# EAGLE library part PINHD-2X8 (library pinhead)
PIN HEADER
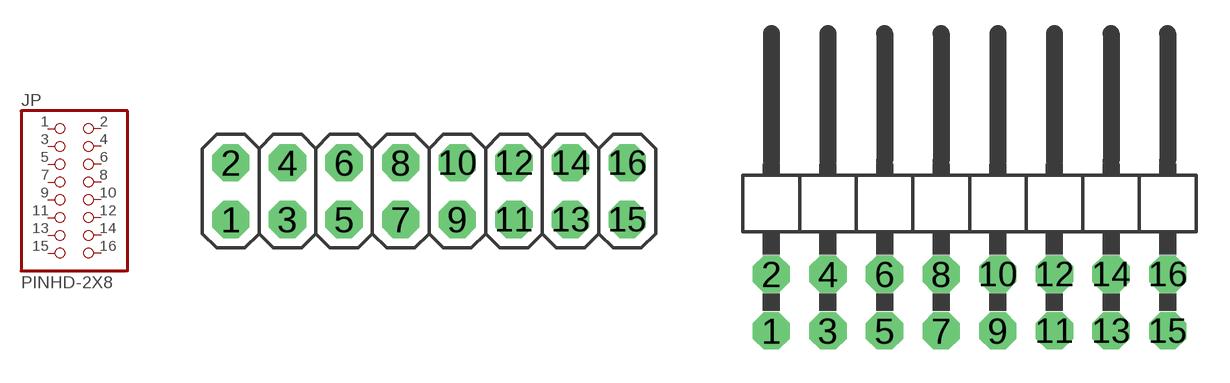
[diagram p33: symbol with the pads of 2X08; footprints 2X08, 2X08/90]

Designator prefix JP

## PINHD-2X8  [2X08]
1  1  pas
2  2  pas
3  3  pas
4  4  pas
5  5  pas
6  6  pas
7  7  pas
8  8  pas
9  9  pas
10  10  pas
11  11  pas
12  12  pas
13  13  pas
14  14  pas
15  15  pas
16  16  pas

## PINHD-2X8/90  [2X08/90]
Pads as for 2X08

## Footprint 2X08 (pad centres in mm)
PIN HEADER
drill 1.016 pad 1.67 octagon: 1 -8.89,-1.27; 2 -8.89,1.27; 3 -6.35,-1.27; 4 -6.35,1.27; 5 -3.81,-1.27; 6 -3.81,1.27; 7 -1.27,-1.27; 8 -1.27,1.27; 9 1.27,-1.27; 10 1.27,1.27; 11 3.81,-1.27; 12 3.81,1.27; 13 6.35,-1.27; 14 6.35,1.27; 15 8.89,-1.27; 16 8.89,1.27

## Footprint 2X08/90 (pad centres in mm)
PIN HEADER
drill 1.016 pad 1.67 octagon: 1 -8.89,-6.35; 2 -8.89,-3.81; 3 -6.35,-6.35; 4 -6.35,-3.81; 5 -3.81,-6.35; 6 -3.81,-3.81; 7 -1.27,-6.35; 8 -1.27,-3.81; 9 1.27,-6.35; 10 1.27,-3.81; 11 3.81,-6.35; 12 3.81,-3.81; 13 6.35,-6.35; 14 6.35,-3.81; 15 8.89,-6.35; 16 8.89,-3.81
